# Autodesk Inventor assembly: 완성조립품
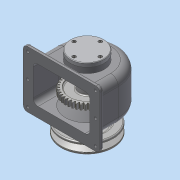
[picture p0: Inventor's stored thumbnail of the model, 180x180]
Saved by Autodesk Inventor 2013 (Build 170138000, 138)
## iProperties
Created: 2015-09
Part Number: 완성조립품
Document SubType Name: Assembly
Designer: Administrator
Author: Administrator
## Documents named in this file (14)
- C:\Users\Administrator\Desktop\450908V1015\완성조립품.iam
- C:\Users\Administrator\Desktop\450908V1015\V-벨트풀리.ipt
- C:\Users\Administrator\Desktop\450908V1015\뒤커버.ipt
- C:\Users\Administrator\Desktop\450908V1015\멈춤나사 - M4x10.ipt
- C:\Users\Administrator\Desktop\450908V1015\베어링 6203.ipt
- C:\Users\Administrator\Desktop\450908V1015\본체.ipt
- C:\Users\Administrator\Desktop\450908V1015\볼트 M3 x 8.ipt
- C:\Users\Administrator\Desktop\450908V1015\볼트 M3 x 10.ipt
- C:\Users\Administrator\Desktop\450908V1015\스퍼기어.ipt
- C:\Users\Administrator\Desktop\450908V1015\앞커버.ipt
- C:\Users\Administrator\Desktop\450908V1015\오일 실 17 32 8.ipt
- C:\Users\Administrator\Desktop\450908V1015\축.ipt
- C:\Users\Administrator\Desktop\450908V1015\키 - 5 x 5 x 18.ipt
- C:\Users\Administrator\Desktop\450908V1015\키 - 6 x 6 x 22.ipt
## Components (9 placed, 3 different names)
1. V-벨트풀리:1
2. ISO 4762 M3 x 8:1
3. ISO 4762 M3 x 8:2
4. ISO 4762 M3 x 8:3
5. ISO 4762 M3 x 8:4
6. ISO 4762 M3 x 10:1
7. ISO 4762 M3 x 10:2
8. ISO 4762 M3 x 10:3
9. ISO 4762 M3 x 10:4
